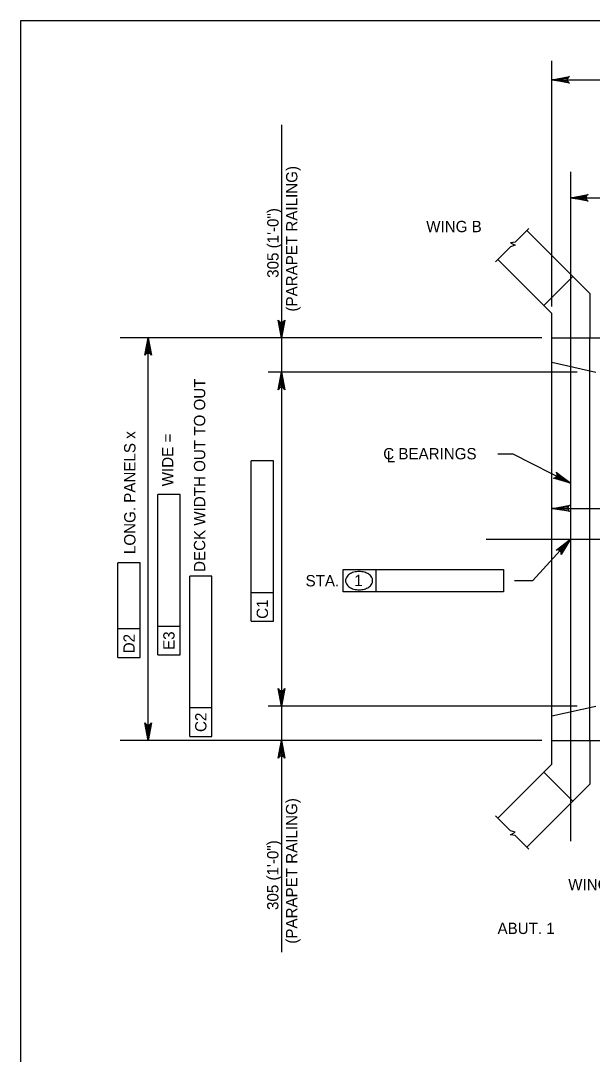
# Model space of a CAD drawing. Extents: x 638268 to 640277, y 295465 to 298435.
# Drawn here: x 639316.5 to 639468, y 297552.5 to 297826.5 of the extents above; entities that cross this region are included whole.
import ezdxf

# ---------------------------------------------------------------- set-up
doc = ezdxf.new("R2010")
doc.units = 0
for name, color, linetype in [('2', 7, 'Continuous'), ('3', 7, 'Continuous'), ('4', 7, 'Continuous')]:
    doc.layers.add(name, color=color, linetype=linetype)

msp = doc.modelspace()

# ---------------------------------------------------------------- linework, layer by layer
at = {"layer": '2'}
for p, q in [((639316.46, 297262.46), (639316.46, 297826.46)), ((639316.46, 297826.46), (640102.46, 297826.46)), ((639467.35, 297754.17), (639450.67, 297770.85)), ((639457.3, 297748.85), (639442.98, 297763.17)), ((639455.15, 297751.01), (639462.83, 297758.69)), ((639467.35, 297754.17), (639467.35, 297742.44)), ((639457.3, 297748.85), (639455.15, 297751.01)), ((639457.3, 297629.47), (639457.3, 297748.85)), ((639457.3, 297742.44), (639650.54, 297742.44)), ((639467.35, 297635.72), (639467.35, 297742.44)), ((639457.3, 297735.93), (639468.98, 297733.32)), ((639457.3, 297642.23), (639468.98, 297644.84)), ((639457.3, 297635.72), (639650.54, 297635.72)), ((639467.35, 297635.72), (639467.35, 297624.16)), ((639457.3, 297629.47), (639442.98, 297615.16)), ((639457.3, 297629.47), (639455.15, 297627.32)), ((639455.15, 297627.32), (639462.83, 297619.63)), ((639467.35, 297624.16), (639450.67, 297607.47))]:
    msp.add_line(p, q, dxfattribs=at)
at = {"layer": '3'}
for p, q in [((639447.57, 297767.75), (639451.21, 297771.4)), ((639442.39, 297762.57), (639446.38, 297766.56)), ((639447.57, 297767.75), (639446.3, 297767.6)), ((639446.3, 297767.6), (639447.6, 297766.95)), ((639447.6, 297766.95), (639446.38, 297766.56)), ((639442.39, 297615.75), (639446.38, 297611.77)), ((639446.3, 297610.73), (639447.6, 297611.38)), ((639447.57, 297610.58), (639446.3, 297610.73)), ((639447.6, 297611.38), (639446.38, 297611.77)), ((639447.57, 297610.58), (639451.21, 297606.93))]:
    msp.add_line(p, q, dxfattribs=at)
at = {"layer": '4'}
for p, q in [((639457.3, 297750.7), (639457.3, 297815.77)), ((639457.3, 297810.78), (639649.71, 297810.78)), ((639385.61, 297798.87), (639385.61, 297579.66)), ((639462.25, 297786.44), (639462.25, 297609)), ((639462.25, 297779.47), (639522.17, 297779.47)), ((639454.66, 297742.44), (639342.85, 297742.44)), ((639350.26, 297635.72), (639350.26, 297742.44)), ((639464.06, 297733.32), (639382.1, 297733.32)), ((639443, 297711.68), (639446.98, 297711.68)), ((639446.98, 297711.68), (639462.25, 297703.92)), ((639377.59, 297667.3), (639377.59, 297709.82)), ((639383.5, 297709.81), (639377.59, 297709.82)), ((639383.5, 297667.29), (639383.5, 297709.81)), ((639352.81, 297658.4), (639352.81, 297700.92)), ((639358.72, 297700.91), (639352.81, 297700.92)), ((639358.72, 297658.39), (639358.72, 297700.91)), ((639457.52, 297697.23), (639650.54, 297697.23)), ((639439.93, 297689.08), (639696.71, 297689.08)), ((639452.28, 297678.1), (639462.25, 297689.03)), ((639342.25, 297657.74), (639342.25, 297682.78)), ((639348.16, 297682.78), (639342.25, 297682.78)), ((639348.16, 297657.73), (639348.16, 297682.78)), ((639361.27, 297636.78), (639361.27, 297679.3)), ((639367.18, 297679.29), (639361.27, 297679.3)), ((639367.18, 297636.77), (639367.18, 297679.29)), ((639401.96, 297681.03), (639444.48, 297681.03)), ((639401.96, 297675.12), (639401.96, 297681.03)), ((639410.71, 297675.12), (639410.71, 297681.03)), ((639444.48, 297681.03), (639444.48, 297675.12)), ((639447.39, 297678.1), (639452.28, 297678.1)), ((639383.5, 297674.85), (639377.59, 297674.86)), ((639444.48, 297675.12), (639401.96, 297675.12)), ((639348.16, 297665.29), (639342.25, 297665.3)), ((639358.72, 297665.95), (639352.81, 297665.96)), ((639377.59, 297667.3), (639383.5, 297667.29)), ((639342.25, 297657.74), (639348.16, 297657.73)), ((639352.81, 297658.4), (639358.72, 297658.39)), ((639367.18, 297644.33), (639361.27, 297644.34)), ((639464.06, 297644.84), (639382.1, 297644.84)), ((639454.66, 297635.72), (639342.85, 297635.72)), ((639361.27, 297636.78), (639367.18, 297636.77))]:
    msp.add_line(p, q, dxfattribs=at)
for points in [[(639457.3, 297810.78), (639461.96, 297811.65), (639461.6, 297811.41), (639461.42, 297811.09), (639461.36, 297810.78), (639461.42, 297810.47), (639461.6, 297810.16), (639461.96, 297809.91), (639457.3, 297810.78), (639461.6, 297810.16), (639461.42, 297810.47), (639457.3, 297810.78), (639461.36, 297810.78), (639461.42, 297811.09), (639457.3, 297810.78), (639461.6, 297811.41)], [(639462.25, 297779.47), (639466.91, 297780.35), (639466.55, 297780.1), (639466.37, 297779.79), (639466.31, 297779.47), (639466.37, 297779.16), (639466.55, 297778.85), (639466.91, 297778.6), (639462.25, 297779.47), (639466.55, 297778.85), (639466.37, 297779.16), (639462.25, 297779.47), (639466.31, 297779.47), (639466.37, 297779.79), (639462.25, 297779.47), (639466.55, 297780.1)], [(639385.61, 297742.44), (639384.73, 297747.1), (639384.98, 297746.75), (639385.29, 297746.56), (639385.61, 297746.51), (639385.92, 297746.56), (639386.23, 297746.75), (639386.48, 297747.1), (639385.61, 297742.44), (639386.23, 297746.75), (639385.92, 297746.56), (639385.61, 297742.44), (639385.61, 297746.51), (639385.29, 297746.56), (639385.61, 297742.44), (639384.98, 297746.75)], [(639350.26, 297742.44), (639351.13, 297737.78), (639350.88, 297738.14), (639350.57, 297738.33), (639350.26, 297738.38), (639349.95, 297738.33), (639349.63, 297738.14), (639349.38, 297737.78), (639350.26, 297742.44), (639349.63, 297738.14), (639349.95, 297738.33), (639350.26, 297742.44), (639350.26, 297738.38), (639350.57, 297738.33), (639350.26, 297742.44), (639350.88, 297738.14)], [(639385.61, 297733.32), (639386.48, 297728.66), (639386.23, 297729.02), (639385.92, 297729.21), (639385.61, 297729.26), (639385.29, 297729.21), (639384.98, 297729.02), (639384.73, 297728.66), (639385.61, 297733.32), (639384.98, 297729.02), (639385.29, 297729.21), (639385.61, 297733.32), (639385.61, 297729.26), (639385.92, 297729.21), (639385.61, 297733.32), (639386.23, 297729.02)], [(639462.25, 297703.92), (639457.7, 297705.26), (639458.13, 297705.31), (639458.44, 297705.51), (639458.63, 297705.76), (639458.72, 297706.07), (639458.7, 297706.43), (639458.49, 297706.81), (639462.25, 297703.92), (639458.7, 297706.43), (639458.72, 297706.07), (639462.25, 297703.92), (639458.63, 297705.76), (639458.44, 297705.51), (639462.25, 297703.92), (639458.13, 297705.31)], [(639457.52, 297697.23), (639462.18, 297698.11), (639461.82, 297697.86), (639461.63, 297697.55), (639461.58, 297697.23), (639461.63, 297696.92), (639461.82, 297696.61), (639462.18, 297696.36), (639457.52, 297697.23), (639461.82, 297696.61), (639461.63, 297696.92), (639457.52, 297697.23), (639461.58, 297697.23), (639461.63, 297697.55), (639457.52, 297697.23), (639461.82, 297697.86)], [(639462.25, 297689.03), (639459.75, 297685), (639459.81, 297685.43), (639459.71, 297685.78), (639459.51, 297686.03), (639459.24, 297686.2), (639458.89, 297686.27), (639458.46, 297686.17), (639462.25, 297689.03), (639458.89, 297686.27), (639459.24, 297686.2), (639462.25, 297689.03), (639459.51, 297686.03), (639459.71, 297685.78), (639462.25, 297689.03), (639459.81, 297685.43)], [(639385.65, 297644.79), (639384.77, 297649.45), (639385.02, 297649.09), (639385.33, 297648.91), (639385.65, 297648.85), (639385.96, 297648.91), (639386.27, 297649.09), (639386.52, 297649.45), (639385.65, 297644.79), (639386.27, 297649.09), (639385.96, 297648.91), (639385.65, 297644.79), (639385.65, 297648.85), (639385.33, 297648.91), (639385.65, 297644.79), (639385.02, 297649.09)], [(639350.26, 297635.72), (639349.38, 297640.38), (639349.63, 297640.02), (639349.95, 297639.83), (639350.26, 297639.78), (639350.57, 297639.83), (639350.88, 297640.02), (639351.13, 297640.38), (639350.26, 297635.72), (639350.88, 297640.02), (639350.57, 297639.83), (639350.26, 297635.72), (639350.26, 297639.78), (639349.95, 297639.83), (639350.26, 297635.72), (639349.63, 297640.02)], [(639385.61, 297635.72), (639386.48, 297631.06), (639386.23, 297631.41), (639385.92, 297631.6), (639385.61, 297631.65), (639385.29, 297631.6), (639384.98, 297631.41), (639384.73, 297631.06), (639385.61, 297635.72), (639384.98, 297631.41), (639385.29, 297631.6), (639385.61, 297635.72), (639385.61, 297631.65), (639385.92, 297631.6), (639385.61, 297635.72), (639386.23, 297631.41)]]:
    msp.add_lwpolyline(points, dxfattribs=at)
for points in [[(639349.78, 297739.61), (639350.73, 297739.61), (639350.26, 297742.44)], [(639349.78, 297638.55), (639350.73, 297638.55), (639350.26, 297635.72)]]:
    msp.add_lwpolyline(points, close=True, dxfattribs=at)
for centre, radius, start, end in [((639404.29, 297678.06), 1.68, 148.5507, 180), ((639405.2, 297677.5), 2.75, 124.109, 148.5507), ((639405.8, 297676.62), 3.82, 105.6708, 124.109), ((639406.2, 297675.22), 5.27, 90, 105.6708), ((639406.2, 297675.22), 5.27, 74.3292, 90), ((639406.59, 297676.62), 3.82, 55.891, 74.3292), ((639407.19, 297677.5), 2.75, 31.4493, 55.891), ((639408.1, 297678.06), 1.68, 0, 31.4493), ((639404.29, 297678.06), 1.68, 180, 211.4493), ((639405.2, 297678.62), 2.75, 211.4493, 235.891), ((639405.8, 297679.51), 3.82, 235.891, 254.3292), ((639406.59, 297679.51), 3.82, 285.6708, 304.109), ((639407.19, 297678.62), 2.75, 304.109, 328.5507), ((639408.1, 297678.06), 1.68, 328.5507, 0), ((639406.2, 297680.91), 5.27, 254.3292, 270), ((639406.2, 297680.91), 5.27, 270, 285.6708)]:
    msp.add_arc(centre, radius, start, end, dxfattribs=at)

# ---------------------------------------------------------------- texts
for s, rotation, p in [('(PARAPET RAILING)', 90, (639389.84, 297749.38)), ('305 (1\'-0")', 90, (639384.84, 297758.31)), ('DECK WIDTH OUT TO OUT', 90, (639365.4, 297680.37)), ('LONG. PANELS x', 90, (639346.9, 297685.11)), ('WIDE =', 90, (639356.94, 297703.07)), ('C1', 89.9382, (639382.04, 297667.95)), ('D2', 89.9382, (639346.7, 297658.82)), ('E3', 89.9382, (639357.26, 297659.71)), ('C2', 89.9382, (639365.72, 297637.96)), ('(PARAPET RAILING)', 90, (639389.8, 297581.87)), ('305 (1\'-0")', 90, (639384.8, 297590.8))]:
    msp.add_text(s, height=3, rotation=rotation, dxfattribs=at).set_placement(p)
for s, p in [('WING B', (639424, 297770.41)), ('C BEARINGS', (639412.6, 297710.21)), ('L', (639413.5, 297709.45)), ('STA.', (639392, 297676.55)), ('1', (639404.9, 297676.61)), ('WING A', (639461.65, 297596.05)), ('ABUT. 1', (639442.9, 297584.43))]:
    msp.add_text(s, height=3, dxfattribs=at).set_placement(p)

doc.saveas('drawing.dxf')
